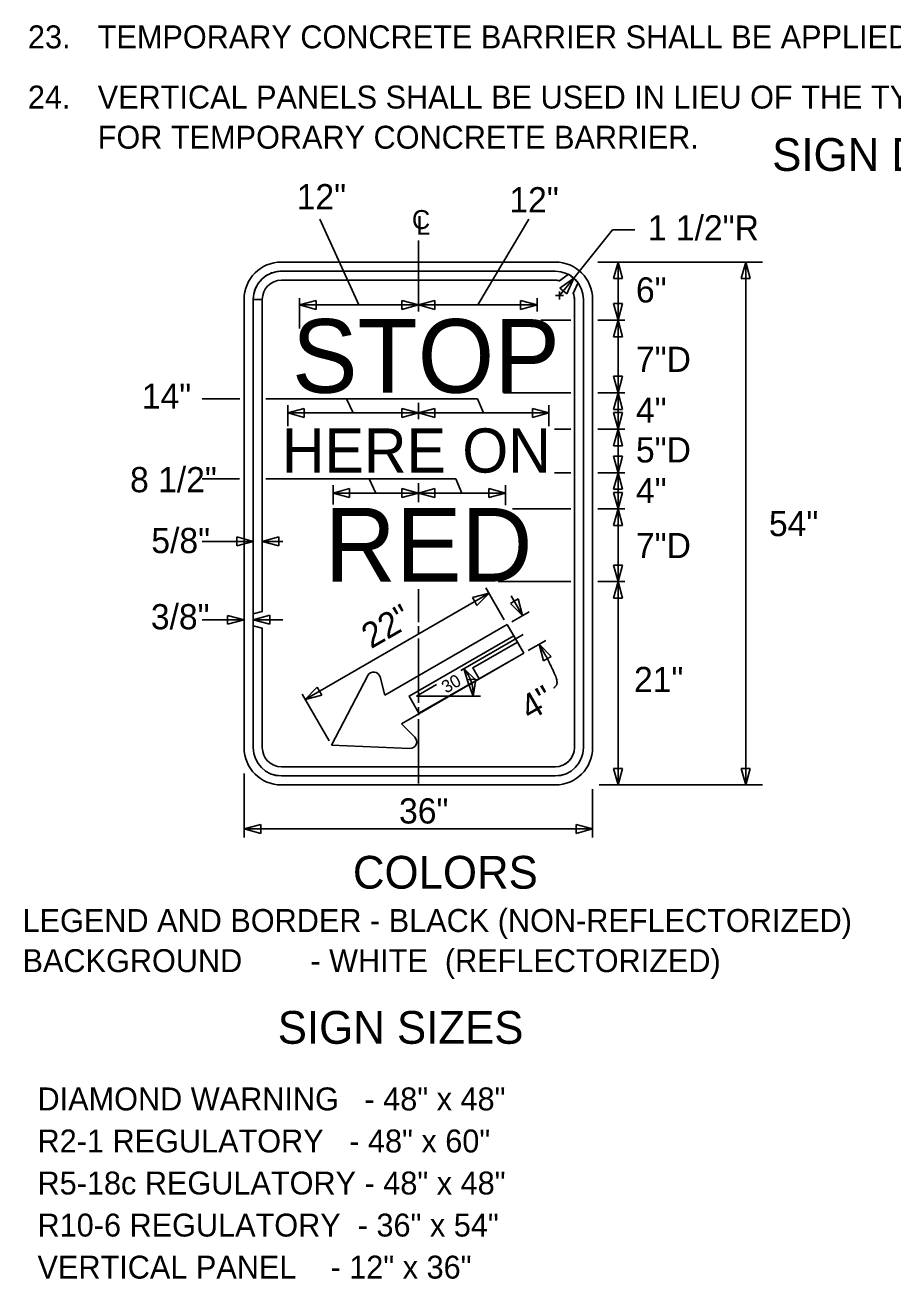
# Model space of a CAD drawing. Extents: x 16733 to 18484, y 7218 to 8208.
# Drawn here: x 17775.1 to 18093.1, y 7243.1 to 7702.3 of the extents above; entities that cross this region are included whole.
import ezdxf

# ---------------------------------------------------------------- set-up
doc = ezdxf.new("R2010")
doc.units = 0
for name, color, linetype in [('MT_SCRATCH_LEVEL_A', 7, 'Continuous'), ('TRAFFIC_SIGNS_PR', 7, 'Continuous'), ('TYPICAL_TEXT_DIMEN_EX', 7, 'Continuous'), ('TYPICAL_TEXT_DIMEN_PR', 7, 'Continuous')]:
    doc.layers.add(name, color=color, linetype=linetype)

msp = doc.modelspace()

# ---------------------------------------------------------------- linework, layer by layer
at = {"layer": 'MT_SCRATCH_LEVEL_A'}
for p, q in [((17919.21, 7597.41), (17919.21, 7623.46)), ((17919.21, 7557.96), (17919.21, 7563.96)), ((17919.21, 7527.6), (17919.21, 7534.53)), ((17919.21, 7483.63), (17919.21, 7495.76)), ((17919.21, 7479.19), (17919.21, 7482.15)), ((17919.21, 7454.07), (17919.21, 7477.72)), ((17919.21, 7449.64), (17919.21, 7452.59)), ((17919.21, 7424.52), (17919.21, 7448.16))]:
    msp.add_line(p, q, dxfattribs=at)
at = {"layer": 'TRAFFIC_SIGNS_PR'}
for p, q in [((17869.04, 7615.55), (17969.47, 7615.55)), ((17869.04, 7612.23), (17869.57, 7612.23)), ((17869.57, 7612.23), (17969.38, 7612.23)), ((17869.57, 7612.21), (17969.38, 7612.23)), ((17974.19, 7611.11), (17970.99, 7608.63)), ((17974.19, 7611.11), (17971.25, 7608.97)), ((17869.04, 7608.9), (17969.49, 7608.9)), ((17969.49, 7608.9), (17869.04, 7608.9)), ((17976, 7604.05), (17977.77, 7607.98)), ((17977.54, 7607.52), (17976, 7604.05)), ((17855.38, 7437.56), (17855.38, 7601.88)), ((17858.7, 7601.88), (17862.02, 7601.88)), ((17862.03, 7601.88), (17858.7, 7601.88)), ((17858.7, 7437.7), (17858.7, 7601.81)), ((17862.02, 7601.81), (17858.7, 7601.81)), ((17862.02, 7487.55), (17862.02, 7601.81)), ((17976.4, 7437.7), (17976.4, 7601.88)), ((17976.4, 7437.7), (17976.4, 7601.88)), ((17979.73, 7437.7), (17979.73, 7601.88)), ((17979.73, 7601.88), (17979.73, 7437.7)), ((17983.05, 7437.7), (17983.05, 7601.88)), ((17858.71, 7486.66), (17862.02, 7487.55)), ((17858.71, 7483.35), (17858.71, 7485.66)), ((17862.02, 7481.46), (17858.71, 7482.35)), ((17862.02, 7437.7), (17862.02, 7481.46)), ((17951.74, 7482.81), (17906.93, 7456.94)), ((17957.82, 7472.28), (17951.74, 7482.81)), ((17913.01, 7446.41), (17957.82, 7472.28)), ((17900.68, 7464.12), (17887.4, 7438.64)), ((17906.93, 7456.94), (17905.19, 7463.61)), ((17917.91, 7441.56), (17913.01, 7446.41)), ((17887.4, 7438.64), (17916.1, 7437.4)), ((17869.04, 7430.68), (17969.44, 7430.68)), ((17869.04, 7430.68), (17969.44, 7430.68)), ((17869.04, 7427.36), (17969.38, 7427.36)), ((17969.38, 7427.36), (17869.04, 7427.36)), ((17869.04, 7424.03), (17927.91, 7424.03)), ((17869.04, 7424.03), (17927.91, 7424.03)), ((17927.91, 7424.03), (17969.39, 7424.03))]:
    msp.add_line(p, q, dxfattribs=at)
msp.add_lwpolyline([(17858.7, 7437.7), (17858.7, 7601.81), (17862.02, 7601.81), (17862.02, 7487.55), (17858.71, 7486.66), (17858.71, 7482.35), (17862.02, 7481.46), (17862.02, 7437.7)], dxfattribs=at)
for points in [[(17957.82, 7472.28), (17919.44, 7450.29), (17915.82, 7456.61), (17954.2, 7478.6)], [(17957.82, 7472.28), (17941.48, 7462.92), (17939.16, 7466.98), (17955.5, 7476.33)]]:
    msp.add_lwpolyline(points, close=True, dxfattribs=at)
for centre, radius, start, end in [((17869.04, 7601.88), 13.67, 90, 180), ((17969.38, 7601.88), 13.67, 0, 90), ((17869.04, 7601.88), 10.34, 90, 180), ((17869.04, 7601.88), 10.34, 87.0749, 180), ((17969.38, 7601.88), 10.34, 0.0011, 90), ((17969.38, 7601.88), 10.34, 0, 90), ((17962.34, 7593.94), 20.86, 42.2917, 55.3821), ((17969.38, 7601.88), 10.34, 42.6036, 55.6914), ((17869.04, 7601.88), 7.02, 90, 180), ((17869.04, 7601.88), 7.02, 90, 180), ((17969.38, 7601.88), 7.02, 76.1968, 90), ((17969.6, 7605.14), 3.76, 68.3136, 91.7829), ((17972.18, 7602.22), 4.24, 355.4085, 25.5399), ((17969.38, 7601.88), 7.02, 0.0011, 18.4463), ((17902.83, 7462.99), 2.43, 14.678, 152.4708), ((17916.2, 7439.83), 2.43, 267.5292, 45.322), ((17869.04, 7437.7), 13.67, 180, 270), ((17869.04, 7437.7), 10.34, 180, 270), ((17869.04, 7437.7), 10.35, 180, 270), ((17869.04, 7437.7), 7.02, 180, 270), ((17869.04, 7437.7), 7.02, 180, 270), ((17969.38, 7437.7), 10.34, 270, 0), ((17969.38, 7437.7), 7.02, 270, 0), ((17969.38, 7437.7), 13.67, 270, 0), ((17969.38, 7437.7), 10.35, 270, 0), ((17969.38, 7437.7), 7.02, 270.4693, 0)]:
    msp.add_arc(centre, radius, start, end, dxfattribs=at)
at = {"layer": 'TYPICAL_TEXT_DIMEN_EX'}
for p, q in [((17900.68, 7464.12), (17887.4, 7438.64)), ((17906.93, 7456.94), (17905.19, 7463.61)), ((17913.01, 7446.41), (17917.92, 7441.56)), ((17916.1, 7437.4), (17887.4, 7438.64))]:
    msp.add_line(p, q, dxfattribs=at)
for centre, start, end in [((17902.83, 7462.99), 14.6782, 152.471), ((17916.2, 7439.83), 267.5295, 45.3222)]:
    msp.add_arc(centre, 2.43, start, end, dxfattribs=at)
at = {"layer": 'TYPICAL_TEXT_DIMEN_PR'}
for p, q in [((17883.12, 7631.29), (17897.44, 7599.85)), ((17959.68, 7631.29), (17940.99, 7599.85)), ((17976.14, 7609.71), (17990.42, 7627.41)), ((17990.42, 7627.41), (17998.51, 7627.41)), ((17984.97, 7615.55), (18045.29, 7615.55)), ((17990.79, 7609.48), (17992.42, 7615.55)), ((17992.42, 7594.27), (17992.42, 7615.55)), ((17992.42, 7615.55), (17994.04, 7609.48)), ((18037.57, 7609.48), (18039.19, 7615.55)), ((18039.19, 7424.03), (18039.19, 7615.55)), ((18039.19, 7615.55), (18040.82, 7609.48)), ((17970.98, 7603.31), (17976.14, 7609.71)), ((17971.07, 7606.01), (17976.14, 7609.71)), ((17976.14, 7609.71), (17973.6, 7603.97)), ((17992.42, 7609.48), (17990.79, 7609.48)), ((17994.04, 7609.48), (17992.42, 7609.48)), ((18039.19, 7609.48), (18037.57, 7609.48)), ((18040.82, 7609.48), (18039.19, 7609.48)), ((17970.98, 7601.84), (17970.98, 7604.79)), ((17972.33, 7604.99), (17971.07, 7606.01)), ((17973.6, 7603.97), (17972.33, 7604.99)), ((17875.66, 7591.25), (17875.66, 7602.33)), ((17875.66, 7599.85), (17881.72, 7601.47)), ((17881.72, 7601.47), (17881.72, 7599.85)), ((17913.15, 7599.85), (17913.15, 7601.47)), ((17913.15, 7601.47), (17919.21, 7599.85)), ((17919.21, 7599.85), (17925.28, 7601.47)), ((17925.28, 7601.47), (17925.28, 7599.85)), ((17956.7, 7599.85), (17956.7, 7601.47)), ((17956.7, 7601.47), (17962.77, 7599.85)), ((17956.7, 7599.85), (17956.7, 7601.47)), ((17956.7, 7601.47), (17962.77, 7599.85)), ((17962.77, 7597.41), (17962.77, 7602.33)), ((17969.5, 7603.31), (17972.46, 7603.31)), ((17992.42, 7594.27), (17990.79, 7600.34)), ((17990.79, 7600.34), (17992.42, 7600.34)), ((17992.42, 7600.34), (17994.04, 7600.34)), ((17994.04, 7600.34), (17992.42, 7594.27)), ((17875.66, 7599.85), (17919.21, 7599.85)), ((17881.72, 7598.22), (17875.66, 7599.85)), ((17881.72, 7599.85), (17881.72, 7598.22)), ((17919.21, 7599.85), (17913.15, 7598.22)), ((17913.15, 7598.22), (17913.15, 7599.85)), ((17919.21, 7599.85), (17962.77, 7599.85)), ((17925.28, 7598.22), (17919.21, 7599.85)), ((17925.28, 7599.85), (17925.28, 7598.22)), ((17962.77, 7599.85), (17956.7, 7598.22)), ((17956.7, 7598.22), (17956.7, 7599.85)), ((17962.77, 7599.85), (17956.7, 7598.22)), ((17956.7, 7598.22), (17956.7, 7599.85)), ((17964.11, 7594.27), (17975.12, 7594.27)), ((17984.97, 7594.27), (17994.9, 7594.27)), ((17990.79, 7588.2), (17992.42, 7594.27)), ((17992.42, 7567.67), (17992.42, 7594.27)), ((17992.42, 7594.27), (17994.04, 7588.2)), ((17992.42, 7588.2), (17990.79, 7588.2)), ((17994.04, 7588.2), (17992.42, 7588.2)), ((17992.42, 7567.67), (17990.79, 7573.74)), ((17990.79, 7573.74), (17992.42, 7573.74)), ((17992.42, 7573.74), (17994.04, 7573.74)), ((17994.04, 7573.74), (17992.42, 7567.67)), ((17853.79, 7565.43), (17839.99, 7565.43)), ((17940.93, 7565.43), (17863.31, 7565.43)), ((17892.91, 7565.43), (17895.27, 7560.29)), ((17940.93, 7565.43), (17943.15, 7560.29)), ((17950.37, 7567.67), (17975.12, 7567.67)), ((17984.97, 7567.67), (17994.9, 7567.67)), ((17990.79, 7561.6), (17992.42, 7567.67)), ((17992.42, 7554.37), (17992.42, 7567.67)), ((17992.42, 7567.67), (17994.04, 7561.6)), ((17871.33, 7555.48), (17871.33, 7563.15)), ((17871.33, 7560.29), (17877.4, 7561.91)), ((17871.33, 7560.29), (17919.21, 7560.29)), ((17877.4, 7558.66), (17871.33, 7560.29)), ((17877.4, 7561.91), (17877.4, 7560.29)), ((17877.4, 7560.29), (17877.4, 7558.66)), ((17913.15, 7560.29), (17913.15, 7561.91)), ((17913.15, 7561.91), (17919.21, 7560.29)), ((17919.21, 7560.29), (17913.15, 7558.66)), ((17913.15, 7558.66), (17913.15, 7560.29)), ((17919.21, 7560.29), (17925.28, 7561.91)), ((17919.21, 7560.29), (17967.09, 7560.29)), ((17925.28, 7558.66), (17919.21, 7560.29)), ((17925.28, 7561.91), (17925.28, 7560.29)), ((17925.28, 7560.29), (17925.28, 7558.66)), ((17961.03, 7560.29), (17961.03, 7561.91)), ((17961.03, 7561.91), (17967.09, 7560.29)), ((17967.09, 7560.29), (17961.03, 7558.66)), ((17961.03, 7558.66), (17961.03, 7560.29)), ((17967.09, 7555.48), (17967.09, 7563.15)), ((17992.42, 7561.6), (17990.79, 7561.6)), ((17992.42, 7554.37), (17990.79, 7560.44)), ((17990.79, 7560.44), (17992.42, 7560.44)), ((17994.04, 7561.6), (17992.42, 7561.6)), ((17992.42, 7560.44), (17994.04, 7560.44)), ((17994.04, 7560.44), (17992.42, 7554.37)), ((17969.1, 7554.37), (17975.12, 7554.37)), ((17984.97, 7554.37), (17994.9, 7554.37)), ((17990.79, 7548.3), (17992.42, 7554.37)), ((17992.42, 7538.41), (17992.42, 7554.37)), ((17992.42, 7554.37), (17994.04, 7548.3)), ((17992.42, 7548.3), (17990.79, 7548.3)), ((17994.04, 7548.3), (17992.42, 7548.3)), ((17992.42, 7538.41), (17990.79, 7544.48)), ((17990.79, 7544.48), (17992.42, 7544.48)), ((17992.42, 7544.48), (17994.04, 7544.48)), ((17994.04, 7544.48), (17992.42, 7538.41)), ((17853.62, 7536.15), (17839.99, 7536.15)), ((17932.92, 7536.15), (17863.31, 7536.15)), ((17901.2, 7536.15), (17903.59, 7530.95)), ((17932.92, 7536.15), (17935.17, 7530.95)), ((17969.1, 7538.41), (17975.12, 7538.41)), ((17984.97, 7538.41), (17994.9, 7538.41)), ((17990.79, 7532.34), (17992.42, 7538.41)), ((17992.42, 7525.11), (17992.42, 7538.41)), ((17992.42, 7538.41), (17994.04, 7532.34)), ((17887.96, 7526.71), (17887.96, 7533.81)), ((17887.96, 7530.95), (17894.03, 7532.58)), ((17894.03, 7532.58), (17894.03, 7530.95)), ((17913.15, 7530.95), (17913.15, 7532.58)), ((17913.15, 7532.58), (17919.21, 7530.95)), ((17919.21, 7530.95), (17925.28, 7532.58)), ((17925.28, 7532.58), (17925.28, 7530.95)), ((17945.07, 7530.95), (17945.07, 7532.58)), ((17945.07, 7532.58), (17951.13, 7530.95)), ((17951.13, 7526.5), (17951.13, 7533.81)), ((17992.42, 7532.34), (17990.79, 7532.34)), ((17992.42, 7525.11), (17990.79, 7531.18)), ((17990.79, 7531.18), (17992.42, 7531.18)), ((17994.04, 7532.34), (17992.42, 7532.34)), ((17992.42, 7531.18), (17994.04, 7531.18)), ((17994.04, 7531.18), (17992.42, 7525.11)), ((17887.96, 7530.95), (17919.21, 7530.95)), ((17894.03, 7529.32), (17887.96, 7530.95)), ((17894.03, 7530.95), (17894.03, 7529.32)), ((17919.21, 7530.95), (17913.15, 7529.32)), ((17913.15, 7529.32), (17913.15, 7530.95)), ((17919.21, 7530.95), (17951.13, 7530.95)), ((17925.28, 7529.32), (17919.21, 7530.95)), ((17925.28, 7530.95), (17925.28, 7529.32)), ((17951.13, 7530.95), (17945.07, 7529.32)), ((17945.07, 7529.32), (17945.07, 7530.95)), ((17953.73, 7525.11), (17975.12, 7525.11)), ((17984.97, 7525.11), (17994.9, 7525.11)), ((17990.79, 7519.04), (17992.42, 7525.11)), ((17992.42, 7498.51), (17992.42, 7525.11)), ((17992.42, 7525.11), (17994.04, 7519.04)), ((17992.42, 7519.04), (17990.79, 7519.04)), ((17994.04, 7519.04), (17992.42, 7519.04)), ((17858.71, 7513.25), (17839.99, 7513.25)), ((17852.64, 7513.25), (17852.64, 7514.88)), ((17852.64, 7514.88), (17858.71, 7513.25)), ((17858.71, 7513.25), (17852.64, 7511.63)), ((17852.64, 7511.63), (17852.64, 7513.25)), ((17868.09, 7514.88), (17862.02, 7513.25)), ((17862.02, 7513.25), (17868.09, 7511.63)), ((17869.5, 7513.25), (17862.02, 7513.25)), ((17868.09, 7513.25), (17868.09, 7514.88)), ((17868.09, 7511.63), (17868.09, 7513.25)), ((17992.42, 7498.51), (17990.79, 7504.58)), ((17990.79, 7504.58), (17992.42, 7504.58)), ((17992.42, 7504.58), (17994.04, 7504.58)), ((17994.04, 7504.58), (17992.42, 7498.51)), ((17950.72, 7484.57), (17943.99, 7496.22)), ((17948.47, 7498.51), (17975.12, 7498.51)), ((17984.97, 7498.51), (17994.9, 7498.51)), ((17990.79, 7492.44), (17992.42, 7498.51)), ((17992.42, 7424.03), (17992.42, 7498.51)), ((17992.42, 7498.51), (17994.04, 7492.44)), ((17877.74, 7455.36), (17945.13, 7494.26)), ((17939.06, 7492.64), (17945.13, 7494.26)), ((17939.87, 7491.23), (17939.06, 7492.64)), ((17940.69, 7489.82), (17939.87, 7491.23)), ((17945.13, 7494.26), (17940.69, 7489.82)), ((17952.97, 7490.53), (17954.38, 7491.34)), ((17957.41, 7486.09), (17952.97, 7490.53)), ((17957.41, 7486.09), (17953.25, 7493.29)), ((17954.38, 7491.34), (17955.79, 7492.15)), ((17955.79, 7492.15), (17957.41, 7486.09)), ((17992.42, 7492.44), (17990.79, 7492.44)), ((17994.04, 7492.44), (17992.42, 7492.44)), ((17849.31, 7484.51), (17849.31, 7486.14)), ((17849.31, 7486.14), (17855.38, 7484.51)), ((17864.78, 7486.19), (17858.71, 7484.56)), ((17864.78, 7484.56), (17864.78, 7486.19)), ((17953.42, 7483.78), (17959.81, 7487.47)), ((17855.38, 7484.51), (17839.99, 7484.51)), ((17855.38, 7484.51), (17849.31, 7482.89)), ((17849.31, 7482.89), (17849.31, 7484.51)), ((17858.71, 7484.56), (17864.78, 7482.93)), ((17869.5, 7484.56), (17858.71, 7484.56)), ((17864.78, 7482.93), (17864.78, 7484.56)), ((17934.74, 7465.98), (17957.62, 7479.19)), ((17959.5, 7473.25), (17965.89, 7476.94)), ((17965.58, 7471.94), (17963.49, 7475.55)), ((17965.12, 7469.49), (17963.49, 7475.55)), ((17963.49, 7475.55), (17967.94, 7471.11)), ((17966.53, 7470.3), (17965.12, 7469.49)), ((17967.94, 7471.11), (17966.53, 7470.3)), ((17937.7, 7460.62), (17935.89, 7466.64)), ((17935.89, 7466.64), (17940.46, 7462.33)), ((17937.1, 7462.49), (17938.72, 7462.65)), ((17939.33, 7456.62), (17937.1, 7462.49)), ((17938.72, 7462.65), (17940.33, 7462.82)), ((17940.46, 7462.33), (17939.08, 7461.48)), ((17940.33, 7462.82), (17939.33, 7456.62)), ((17877.74, 7455.36), (17882.19, 7459.8)), ((17882.19, 7459.8), (17883, 7458.39)), ((17883, 7458.39), (17883.81, 7456.98)), ((17918.54, 7456.62), (17925.9, 7460.87)), ((17939.08, 7461.48), (17937.7, 7460.62)), ((17886.53, 7440.15), (17876.61, 7457.32)), ((17883.81, 7456.98), (17877.74, 7455.36)), ((17918.54, 7456.62), (17941.98, 7456.62)), ((17992.42, 7424.03), (17990.79, 7430.1)), ((17990.79, 7430.1), (17992.42, 7430.1)), ((17992.42, 7430.1), (17994.04, 7430.1)), ((17994.04, 7430.1), (17992.42, 7424.03)), ((18039.19, 7424.03), (18037.57, 7430.1)), ((18037.57, 7430.1), (18039.19, 7430.1)), ((18039.19, 7430.1), (18040.82, 7430.1)), ((18040.82, 7430.1), (18039.19, 7424.03)), ((17855.38, 7404.85), (17855.38, 7428.18)), ((17983.05, 7404.85), (17983.05, 7422.51)), ((17985.5, 7424.03), (18045.29, 7424.03)), ((17855.38, 7407.93), (17861.44, 7409.55)), ((17855.38, 7407.93), (17983.05, 7407.93)), ((17861.44, 7406.3), (17855.38, 7407.93)), ((17861.44, 7409.55), (17861.44, 7407.93)), ((17861.44, 7407.93), (17861.44, 7406.3)), ((17976.99, 7407.93), (17976.99, 7409.55)), ((17976.99, 7409.55), (17983.05, 7407.93)), ((17983.05, 7407.93), (17976.99, 7406.3)), ((17976.99, 7406.3), (17976.99, 7407.93))]:
    msp.add_line(p, q, dxfattribs=at)
msp.add_arc((17924.98, 7457.28), 14.37, 357.3664, 40.6242, dxfattribs=at)
msp.add_open_spline([(17965.58, 7471.94), (17968.74, 7466.05), (17970.44, 7461.26), (17968.93, 7459.57), (17968.93, 7459.57)], degree=2, dxfattribs=at)

# ---------------------------------------------------------------- texts
at = {"layer": 'TYPICAL_TEXT_DIMEN_EX'}
for s, height, p in [('STOP', 26.972, (17872.89, 7567.69)), ('HERE ON', 16.181, (17869.2, 7538.44)), ('RED', 26.968, (17884.9, 7498.55))]:
    msp.add_text(s, height=height, dxfattribs=at).set_placement(p)
at = {"layer": 'TYPICAL_TEXT_DIMEN_PR'}
for s, height, p in [('23.', 8.4, (17776.14, 7693.82)), ('TEMPORARY CONCRETE BARRIER SHALL BE APPLIED AS PER THE CURRENT STANDARD PLAN.', 8.4, (17801.7, 7693.82)), ('24.', 8.4, (17776.13, 7671.77)), ('VERTICAL PANELS SHALL BE USED IN LIEU OF THE TYPE B HIGH INTENSITY LIGHT SHOWN IN THE STANDARD PLAN ', 8.4, (17801.7, 7671.77)), ('FOR TEMPORARY CONCRETE BARRIER.', 8.4, (17801.7, 7657.07)), ('SIGN DETAIL', 12, (18048.89, 7648.94)), ('12" ', 9.222, (17874.64, 7634.88)), ('12"', 9.222, (17952.58, 7633.76)), ('1 1/2"R', 9.222, (18003.31, 7623.47)), ('6"', 9.222, (17998.96, 7600.74)), ('7"D', 9.222, (17998.96, 7575.32)), ('14"', 9.222, (17817.88, 7561.8)), ('4"', 9.222, (17998.96, 7556.72)), ('5"D', 9.222, (17998.96, 7542.15)), ('8 1/2"', 9.222, (17813.56, 7531.25)), ('4"', 9.222, (17998.96, 7527.26)), ('54"', 9.222, (18047.7, 7515.17)), ('5/8"', 9.222, (17821.36, 7508.95)), ('7"D', 9.222, (17998.96, 7507.11)), ('3/8"', 9.222, (17821.18, 7481.05)), ('21"', 9.222, (17998.24, 7458.06)), ('36" ', 9.222, (17912.14, 7409.92)), ('COLORS', 12, (17895.23, 7386.06)), ('LEGEND AND BORDER - BLACK (NON-REFLECTORIZED)', 8.4, (17774.16, 7370.2)), ('BACKGROUND        - WHITE  (REFLECTORIZED)', 8.4, (17774.16, 7355.5)), ('SIGN SIZES', 12, (17867.69, 7329.25)), ('DIAMOND WARNING   - 48" x 48"', 8.4, (17779.65, 7304.85)), ('R2-1 REGULATORY   - 48" x 60"', 8.4, (17779.65, 7289.45)), ('R5-18c REGULATORY - 48" x 48"', 8.4, (17779.65, 7274.05)), ('R10-6 REGULATORY  - 36" x 54"', 8.4, (17779.65, 7258.65)), ('VERTICAL PANEL    - 12" x 36"', 8.4, (17779.65, 7243.25))]:
    msp.add_text(s, height=height, dxfattribs=at).set_placement(p)
for s, height, rotation, p in [('C', 6.93, 0, (17916.85, 7627.66)), ('L', 6.93, 0, (17918.41, 7625.53)), ('22"', 9.222, 29.9375, (17901.88, 7473.74)), ('30', 4.618, 30, (17929.41, 7457.44)), ('4"', 9.222, 29.9998, (17960.07, 7447.4))]:
    msp.add_text(s, height=height, rotation=rotation, dxfattribs=at).set_placement(p)

doc.saveas('drawing.dxf')
